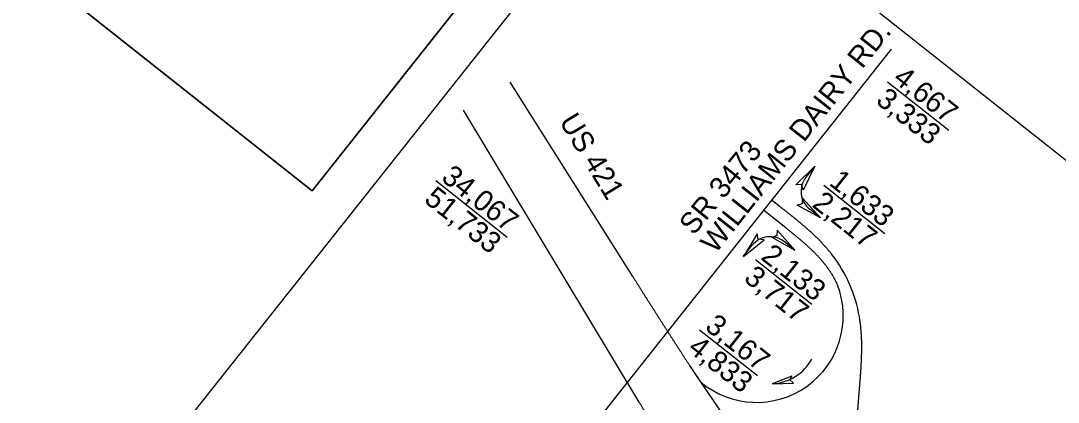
# Model space of a CAD drawing. Extents: x 1771636 to 1784627, y 798645 to 819978.
# Drawn here: x 1783444.1 to 1783789.1, y 812041.9 to 812168.9 of the extents above; entities that cross this region are included whole.
import ezdxf

# ---------------------------------------------------------------- set-up
doc = ezdxf.new("R2010")
doc.units = 0
for name, color, linetype in [('Exist Structure Minor Footbridge', 7, 'Continuous'), ('Exist Utilities Power Joint Use Telephone CELL', 7, 'Continuous'), ('Exist Utilities Telephone Pole CELL', 7, 'Continuous'), ('Exist Vegetation Woods Line', 7, 'Continuous')]:
    doc.layers.add(name, color=color, linetype=linetype)

msp = doc.modelspace()

# ---------------------------------------------------------------- linework, layer by layer
at = {"layer": 'Exist Structure Minor Footbridge'}
for p, q in [((1783733.54, 812159.45), (1783616.05, 812011.05)), ((1783647.55, 812083.81), (1783606.83, 812148.43)), ((1783732.27, 812148.6), (1783752.67, 812132.45)), ((1783649.72, 812041.95), (1783591.33, 812139.12)), ((1783708.11, 812120.5), (1783705.13, 812116.79)), ((1783582.05, 812115.69), (1783605.84, 812096.85)), ((1783711.08, 812114.18), (1783731.39, 812098.1)), ((1783696.62, 812106.95), (1783693.74, 812109.19)), ((1783698.46, 812099.94), (1783691.08, 812105.82)), ((1783710.02, 812103.36), (1783706.41, 812106.2)), ((1783701.45, 812092.54), (1783697.86, 812095.4)), ((1783684.33, 812090.47), (1783687.26, 812094.21)), ((1783688.36, 812089.45), (1783707.16, 812074.57)), ((1783669.74, 812066.1), (1783689.01, 812050.85))]:
    msp.add_line(p, q, dxfattribs=at)
for points in [[(1783481.26, 812012.88), (1783654.22, 812231.34), (1783891.37, 812043.59), (1783718.41, 811825.12)], [(1783701.84, 812114.3), (1783708.12, 812120.49), (1783704.27, 812112.52), (1783703.65, 812114.35)], [(1783704.06, 812109.85), (1783710.02, 812103.36), (1783702.2, 812107.49), (1783704.05, 812108.05)], [(1783688.93, 812097.99), (1783684.34, 812090.46), (1783691.21, 812096.03), (1783689.29, 812096.22)], [(1783693.76, 812096.85), (1783701.45, 812092.54), (1783695.64, 812099.2), (1783695.52, 812097.27)], [(1783700.47, 812050.68), (1783693.91, 812048.08), (1783700.98, 812048.33), (1783699.85, 812049.38)]]:
    msp.add_lwpolyline(points, close=True, dxfattribs=at)
for centre, radius, start, end in [((1783711.04, 812112.1), 7.5, 141.6309, 231.8342), ((1783693.18, 812089.54), 7.5, 51.4277, 141.6309), ((1783676.74, 812062.4), 46.88, 9.7249, 37.756), ((1783688.74, 812070.72), 28.82, 229.6953, 21.0453), ((1784414.38, 812546.24), 895.25, 213.34167, 224.65417), ((1783693.02, 812064.28), 16.23, 273.1409, 330.5289)]:
    msp.add_arc(centre, radius, start, end, dxfattribs=at)
for points in [[(1783713.8, 812091.1), (1783713.6, 812091.35), (1783713.4, 812091.6), (1783713.21, 812091.85), (1783713.01, 812092.09), (1783712.81, 812092.34), (1783712.6, 812092.58), (1783712.4, 812092.82), (1783712.19, 812093.06), (1783711.99, 812093.3), (1783711.78, 812093.54), (1783711.57, 812093.78), (1783711.36, 812094.01), (1783711.14, 812094.25), (1783710.93, 812094.48), (1783710.71, 812094.71), (1783710.5, 812094.95), (1783710.28, 812095.18), (1783710.06, 812095.4), (1783709.84, 812095.63), (1783709.62, 812095.86), (1783709.4, 812096.08), (1783709.17, 812096.31), (1783708.95, 812096.53), (1783708.72, 812096.75), (1783708.5, 812096.98), (1783708.27, 812097.2), (1783708.04, 812097.42), (1783707.81, 812097.63), (1783707.58, 812097.85), (1783707.35, 812098.07), (1783707.12, 812098.28), (1783706.88, 812098.5), (1783706.65, 812098.71), (1783706.42, 812098.92), (1783706.18, 812099.14), (1783705.94, 812099.35), (1783705.71, 812099.56), (1783705.47, 812099.77), (1783705.23, 812099.98), (1783704.99, 812100.18), (1783704.75, 812100.39), (1783704.51, 812100.6), (1783704.27, 812100.8), (1783704.03, 812101.01), (1783703.79, 812101.21), (1783703.55, 812101.42), (1783703.3, 812101.62), (1783703.06, 812101.82), (1783702.82, 812102.02), (1783702.57, 812102.23), (1783702.33, 812102.43), (1783702.08, 812102.63), (1783701.84, 812102.83), (1783701.59, 812103.03), (1783701.34, 812103.22), (1783701.1, 812103.42), (1783700.85, 812103.62), (1783700.6, 812103.82), (1783700.35, 812104.02), (1783700.11, 812104.21), (1783699.86, 812104.41), (1783699.61, 812104.61), (1783699.36, 812104.8), (1783699.11, 812105), (1783698.86, 812105.19), (1783698.61, 812105.39), (1783698.36, 812105.59), (1783698.12, 812105.78), (1783697.87, 812105.98), (1783697.62, 812106.17), (1783697.37, 812106.37), (1783697.12, 812106.56), (1783696.87, 812106.75), (1783696.62, 812106.95)], [(1783715.64, 812081.07), (1783715.49, 812081.39), (1783715.34, 812081.7), (1783715.19, 812082.02), (1783715.04, 812082.33), (1783714.88, 812082.64), (1783714.71, 812082.94), (1783714.55, 812083.25), (1783714.38, 812083.55), (1783714.2, 812083.86), (1783714.03, 812084.16), (1783713.84, 812084.45), (1783713.66, 812084.75), (1783713.47, 812085.04), (1783713.28, 812085.33), (1783713.09, 812085.62), (1783712.89, 812085.91), (1783712.69, 812086.2), (1783712.49, 812086.48), (1783712.29, 812086.76), (1783712.08, 812087.04), (1783711.87, 812087.32), (1783711.66, 812087.6), (1783711.44, 812087.87), (1783711.22, 812088.14), (1783711, 812088.41), (1783710.78, 812088.68), (1783710.56, 812088.95), (1783710.33, 812089.21), (1783710.1, 812089.48), (1783709.87, 812089.74), (1783709.64, 812090), (1783709.4, 812090.25), (1783709.17, 812090.51), (1783708.93, 812090.76), (1783708.69, 812091.01), (1783708.44, 812091.26), (1783708.2, 812091.51), (1783707.96, 812091.76), (1783707.71, 812092.01), (1783707.46, 812092.25), (1783707.21, 812092.49), (1783706.96, 812092.74), (1783706.71, 812092.98), (1783706.45, 812093.21), (1783706.2, 812093.45), (1783705.94, 812093.69), (1783705.68, 812093.92), (1783705.43, 812094.16), (1783705.17, 812094.39), (1783704.91, 812094.62), (1783704.64, 812094.85), (1783704.38, 812095.08), (1783704.12, 812095.31), (1783703.85, 812095.53), (1783703.59, 812095.76), (1783703.32, 812095.98), (1783703.06, 812096.21), (1783702.79, 812096.43), (1783702.52, 812096.66), (1783702.25, 812096.88), (1783701.98, 812097.1), (1783701.71, 812097.32), (1783701.45, 812097.54), (1783701.17, 812097.76), (1783700.9, 812097.98), (1783700.63, 812098.2), (1783700.36, 812098.42), (1783700.09, 812098.64), (1783699.82, 812098.85), (1783699.55, 812099.07), (1783699.27, 812099.29), (1783699, 812099.51), (1783698.73, 812099.72), (1783698.46, 812099.94)], [(1783647.55, 812083.81), (1783647.8, 812083.4), (1783648.06, 812083), (1783648.31, 812082.6), (1783648.56, 812082.2), (1783648.82, 812081.8), (1783649.07, 812081.39), (1783649.32, 812080.99), (1783649.58, 812080.59), (1783649.83, 812080.19), (1783650.08, 812079.79), (1783650.34, 812079.39), (1783650.59, 812078.98), (1783650.84, 812078.58), (1783651.1, 812078.18), (1783651.35, 812077.78), (1783651.6, 812077.38), (1783651.86, 812076.97), (1783652.11, 812076.57), (1783652.37, 812076.17), (1783652.62, 812075.77), (1783652.87, 812075.37), (1783653.13, 812074.97), (1783653.38, 812074.57), (1783653.64, 812074.16), (1783653.89, 812073.76), (1783654.14, 812073.36), (1783654.4, 812072.96), (1783654.65, 812072.56), (1783654.91, 812072.16), (1783655.16, 812071.76), (1783655.42, 812071.36), (1783655.67, 812070.95), (1783655.93, 812070.55), (1783656.18, 812070.15), (1783656.44, 812069.75), (1783656.69, 812069.35), (1783656.95, 812068.95), (1783657.2, 812068.55), (1783657.46, 812068.15), (1783657.71, 812067.75), (1783657.97, 812067.35), (1783658.22, 812066.95), (1783658.48, 812066.55), (1783658.74, 812066.15), (1783658.99, 812065.75), (1783659.25, 812065.35), (1783659.5, 812064.95), (1783659.76, 812064.55), (1783660.02, 812064.15), (1783660.27, 812063.75), (1783660.53, 812063.35), (1783660.79, 812062.95), (1783661.05, 812062.55), (1783661.3, 812062.15), (1783661.56, 812061.75), (1783661.82, 812061.35), (1783662.08, 812060.95), (1783662.33, 812060.55), (1783662.59, 812060.15), (1783662.85, 812059.76), (1783663.11, 812059.36), (1783663.37, 812058.96), (1783663.63, 812058.56), (1783663.89, 812058.16), (1783664.14, 812057.76), (1783664.4, 812057.37), (1783664.66, 812056.97), (1783664.92, 812056.57), (1783665.18, 812056.17), (1783665.44, 812055.78), (1783665.7, 812055.38), (1783665.96, 812054.98), (1783666.23, 812054.58), (1783666.49, 812054.19)], [(1783723.01, 812046.95), (1783723.03, 812047.26), (1783723.06, 812047.58), (1783723.08, 812047.89), (1783723.11, 812048.21), (1783723.13, 812048.52), (1783723.16, 812048.84), (1783723.18, 812049.16), (1783723.21, 812049.47), (1783723.23, 812049.79), (1783723.26, 812050.1), (1783723.28, 812050.42), (1783723.3, 812050.73), (1783723.33, 812051.05), (1783723.35, 812051.37), (1783723.37, 812051.68), (1783723.39, 812052), (1783723.42, 812052.31), (1783723.44, 812052.63), (1783723.46, 812052.95), (1783723.48, 812053.26), (1783723.5, 812053.58), (1783723.51, 812053.89), (1783723.53, 812054.21), (1783723.55, 812054.53), (1783723.57, 812054.84), (1783723.58, 812055.16), (1783723.6, 812055.48), (1783723.61, 812055.79), (1783723.63, 812056.11), (1783723.64, 812056.43), (1783723.65, 812056.74), (1783723.66, 812057.06), (1783723.67, 812057.37), (1783723.68, 812057.69), (1783723.69, 812058.01), (1783723.7, 812058.32), (1783723.7, 812058.64), (1783723.71, 812058.96), (1783723.71, 812059.27), (1783723.72, 812059.59), (1783723.72, 812059.91), (1783723.72, 812060.22), (1783723.72, 812060.54), (1783723.71, 812060.86), (1783723.71, 812061.18), (1783723.71, 812061.49), (1783723.7, 812061.81), (1783723.69, 812062.13), (1783723.69, 812062.44), (1783723.68, 812062.76), (1783723.66, 812063.07), (1783723.65, 812063.39), (1783723.64, 812063.71), (1783723.62, 812064.02), (1783723.6, 812064.34), (1783723.58, 812064.66), (1783723.56, 812064.97), (1783723.54, 812065.29), (1783723.52, 812065.6), (1783723.49, 812065.92), (1783723.46, 812066.24), (1783723.43, 812066.55), (1783723.4, 812066.87), (1783723.37, 812067.18), (1783723.34, 812067.5), (1783723.3, 812067.81), (1783723.26, 812068.12), (1783723.22, 812068.44), (1783723.18, 812068.75), (1783723.13, 812069.07), (1783723.09, 812069.38), (1783723.04, 812069.69), (1783722.99, 812070.01), (1783722.94, 812070.32)], [(1783721.91, 812023.54), (1783721.9, 812023.86), (1783721.9, 812024.18), (1783721.89, 812024.49), (1783721.89, 812024.81), (1783721.89, 812025.13), (1783721.89, 812025.44), (1783721.88, 812025.76), (1783721.88, 812026.08), (1783721.89, 812026.39), (1783721.89, 812026.71), (1783721.89, 812027.03), (1783721.89, 812027.34), (1783721.89, 812027.66), (1783721.9, 812027.98), (1783721.9, 812028.29), (1783721.91, 812028.61), (1783721.92, 812028.93), (1783721.92, 812029.24), (1783721.93, 812029.56), (1783721.94, 812029.88), (1783721.95, 812030.19), (1783721.96, 812030.51), (1783721.97, 812030.83), (1783721.98, 812031.14), (1783721.99, 812031.46), (1783722, 812031.78), (1783722.01, 812032.09), (1783722.03, 812032.41), (1783722.04, 812032.73), (1783722.05, 812033.04), (1783722.07, 812033.36), (1783722.08, 812033.68), (1783722.1, 812033.99), (1783722.11, 812034.31), (1783722.13, 812034.62), (1783722.15, 812034.94), (1783722.16, 812035.26), (1783722.18, 812035.57), (1783722.2, 812035.89), (1783722.22, 812036.21), (1783722.24, 812036.52), (1783722.26, 812036.84), (1783722.28, 812037.15), (1783722.3, 812037.47), (1783722.32, 812037.79), (1783722.34, 812038.1), (1783722.36, 812038.42), (1783722.38, 812038.73), (1783722.4, 812039.05), (1783722.42, 812039.37), (1783722.45, 812039.68), (1783722.47, 812040), (1783722.49, 812040.31), (1783722.51, 812040.63), (1783722.54, 812040.95), (1783722.56, 812041.26), (1783722.58, 812041.58), (1783722.61, 812041.89), (1783722.63, 812042.21), (1783722.66, 812042.53), (1783722.68, 812042.84), (1783722.71, 812043.16), (1783722.73, 812043.47), (1783722.76, 812043.79), (1783722.78, 812044.1), (1783722.81, 812044.42), (1783722.83, 812044.74), (1783722.86, 812045.05), (1783722.88, 812045.37), (1783722.91, 812045.68), (1783722.93, 812046), (1783722.96, 812046.31), (1783722.98, 812046.63), (1783723.01, 812046.95)], [(1783649.72, 812041.95), (1783649.96, 812041.54), (1783650.21, 812041.13), (1783650.45, 812040.73), (1783650.7, 812040.32), (1783650.94, 812039.91), (1783651.19, 812039.5), (1783651.43, 812039.1), (1783651.68, 812038.69), (1783651.92, 812038.28), (1783652.17, 812037.88), (1783652.41, 812037.47), (1783652.66, 812037.06), (1783652.9, 812036.65), (1783653.15, 812036.25), (1783653.39, 812035.84), (1783653.64, 812035.43), (1783653.88, 812035.03), (1783654.13, 812034.62), (1783654.37, 812034.21), (1783654.62, 812033.81), (1783654.86, 812033.4), (1783655.11, 812032.99), (1783655.36, 812032.59), (1783655.6, 812032.18), (1783655.85, 812031.77), (1783656.09, 812031.37), (1783656.34, 812030.96), (1783656.59, 812030.55), (1783656.83, 812030.15), (1783657.08, 812029.74), (1783657.32, 812029.33), (1783657.57, 812028.93), (1783657.82, 812028.52), (1783658.07, 812028.12), (1783658.31, 812027.71), (1783658.56, 812027.31), (1783658.81, 812026.9), (1783659.05, 812026.49), (1783659.3, 812026.09), (1783659.55, 812025.68), (1783659.8, 812025.28), (1783660.05, 812024.87), (1783660.29, 812024.47), (1783660.54, 812024.06), (1783660.79, 812023.66), (1783661.04, 812023.25), (1783661.29, 812022.85), (1783661.54, 812022.44), (1783661.79, 812022.04), (1783662.04, 812021.63), (1783662.29, 812021.23), (1783662.53, 812020.83), (1783662.79, 812020.42), (1783663.04, 812020.02), (1783663.29, 812019.62), (1783663.54, 812019.21), (1783663.79, 812018.81), (1783664.04, 812018.4), (1783664.29, 812018), (1783664.54, 812017.6), (1783664.79, 812017.2), (1783665.04, 812016.79), (1783665.3, 812016.39), (1783665.55, 812015.99), (1783665.8, 812015.59), (1783666.06, 812015.18), (1783666.31, 812014.78), (1783666.56, 812014.38), (1783666.82, 812013.98), (1783667.07, 812013.58), (1783667.32, 812013.18), (1783667.58, 812012.77), (1783667.83, 812012.37), (1783668.09, 812011.97)]]:
    msp.add_spline(points, degree=3, dxfattribs=at)
at = {"layer": 'Exist Utilities Telephone Pole CELL'}
msp.add_lwpolyline([(1783384.75, 813185.41), (1782922.68, 812601.78), (1782968.4, 812565.53), (1783541.01, 812112.27), (1783700.51, 812313.71), (1783949.29, 812116.75), (1783784.11, 811908.02), (1783320.21, 811324), (1783286.6, 811356.67), (1783146.91, 811467.26), (1783125.11, 811467.64), (1783094.07, 811428.44), (1782948.68, 811547.66), (1782956.1, 811557.03), (1782756.79, 811714.83), (1782728.22, 811696.01), (1782447.03, 811920.16), (1782412.5, 811881.47), (1782072.85, 812146.5), (1782110.35, 812188.55), (1781507.48, 812669.12)], dxfattribs=at)
at = {"layer": 'Exist Vegetation Woods Line'}
msp.add_lwpolyline([(1783243.56, 812995.92), (1784039.66, 812365.64), (1783883.72, 812168.66), (1783700.51, 812313.71), (1783541.01, 812112.27), (1782928.12, 812597.5)], close=True, dxfattribs=at)

# ---------------------------------------------------------------- texts
at = {"layer": 'Exist Structure Minor Footbridge'}
for s, rotation, p in [('WILLIAMS DAIRY RD.', 51.5663, (1783675.05, 812091.1)), ('4,667', 321.6312, (1783733.73, 812148.89)), ('3,333', 321.6312, (1783728.04, 812141.7)), ('US 421 ', 301.2885, (1783622.93, 812135.4)), ('SR 3473', 50.7628, (1783667.85, 812097.19)), ('34,067', 321.6312, (1783583.51, 812115.98)), ('1,633', 321.6312, (1783712.54, 812114.47)), ('51,733', 321.6312, (1783577.81, 812108.79)), ('2,217', 321.6312, (1783706.85, 812107.27)), ('2,133', 321.6312, (1783689.82, 812089.75)), ('3,717', 321.6312, (1783684.13, 812082.55)), ('3,167', 321.6312, (1783671.2, 812066.4)), ('4,833', 321.6312, (1783665.5, 812059.2))]:
    msp.add_text(s, height=7, rotation=rotation, dxfattribs=at).set_placement(p)
at = {"layer": 'Exist Utilities Power Joint Use Telephone CELL'}
msp.add_text('TO PLOT FULL SIZE 62"X34"', height=75, rotation=51.6309, dxfattribs=at).set_placement((1783719.07, 811003.39))

doc.saveas('drawing.dxf')
